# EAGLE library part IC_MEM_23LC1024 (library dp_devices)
1Mbit SPI SRAM with Serial dual interface and Serial quad interface
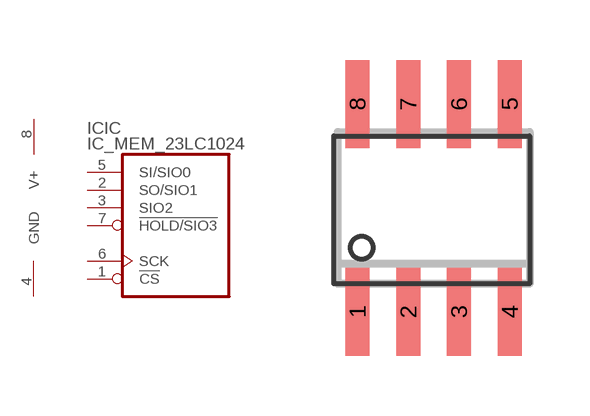
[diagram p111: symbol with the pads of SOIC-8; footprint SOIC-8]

Designator prefix IC; gates IC=SRAM-23LCXXXX SUP=SUPPLY

## IC_MEM_23LC1024  [SOIC-8]
1  IC:!CS  in
2  IC:SO/SIO1
3  IC:SIO2
4  SUP:GND  sup
5  IC:SI/SIO0
6  IC:SCK  in
7  IC:!HOLD/SIO3  in
8  SUP:V+  sup

## Footprint SOIC-8 (pad centres in mm)
smd 0.6 x 2.2: 1 -1.905,-2.6; 2 -0.635,-2.6; 3 0.635,-2.6; 4 1.905,-2.6; 5 1.905,2.6; 6 0.635,2.6; 7 -0.635,2.6; 8 -1.905,2.6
